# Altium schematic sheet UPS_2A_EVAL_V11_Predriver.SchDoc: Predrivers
size A4; CompanyName: Hedgehog OÜ; Revision: 1; SheetNumber: 2; SheetTotal: 6; DrawnBy: Peep Narusberg; Engineer: Peep Narusberg; Organization: Hedgehog OÜ; Address1: Waterloohain 5; Address2: 22769 Hamburg; Address3: Germany; Address4: tmc_info@trinamic.com
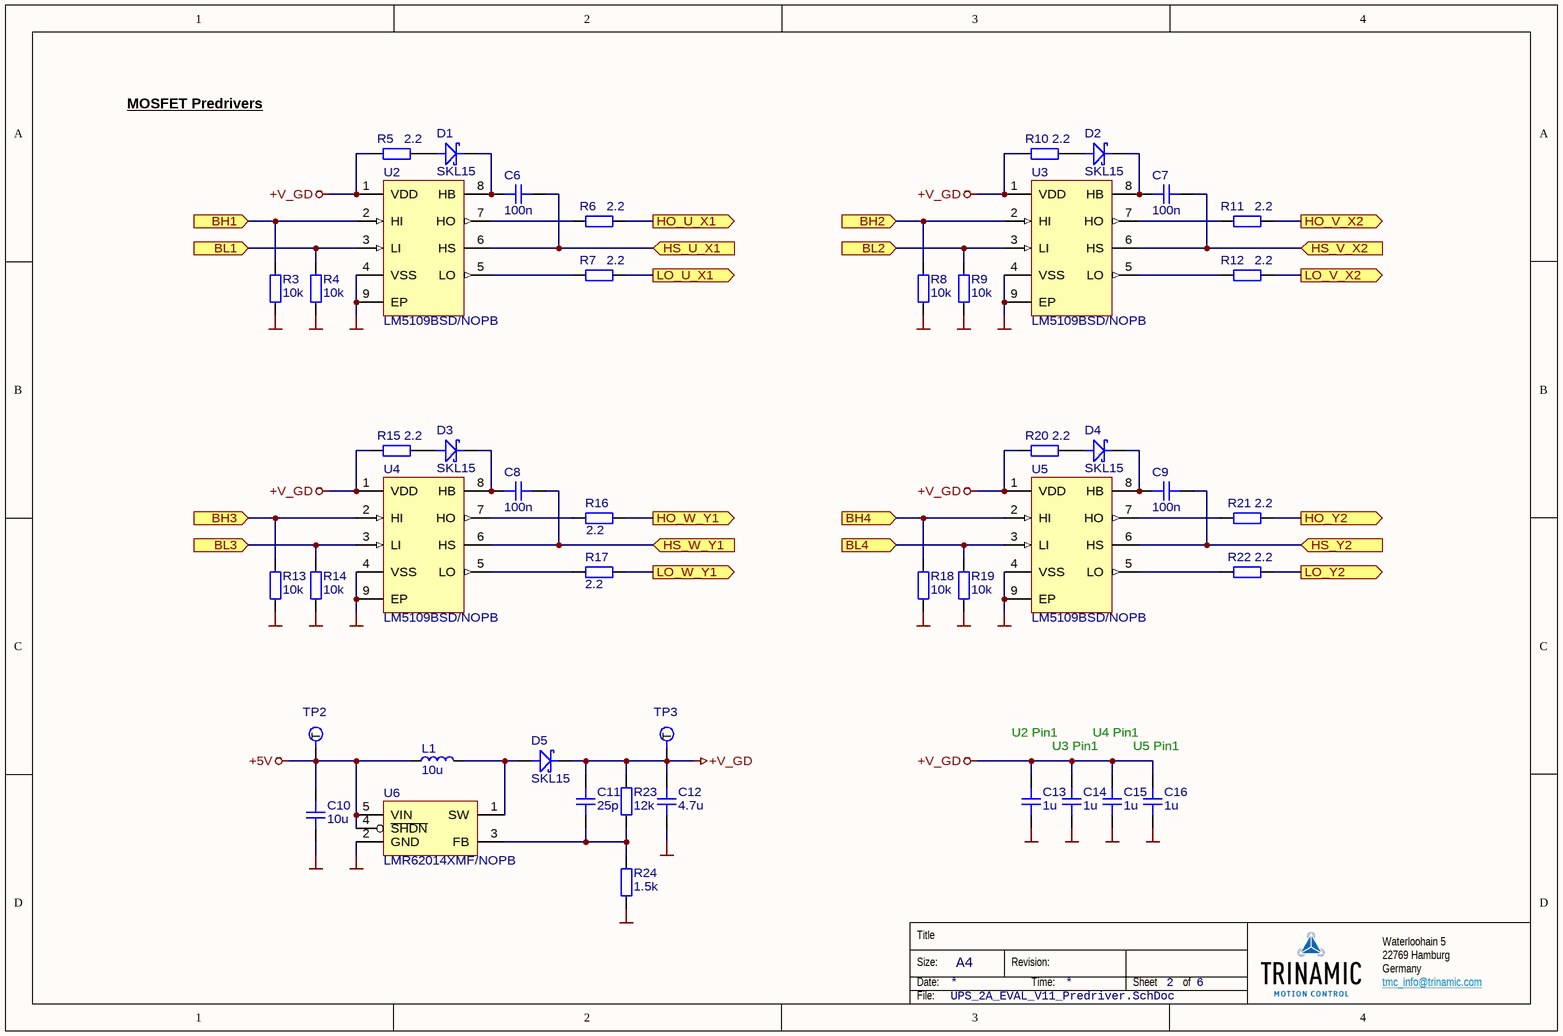
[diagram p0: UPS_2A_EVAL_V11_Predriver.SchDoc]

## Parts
C6  value 100n  [CAPC1608N]  (hidden comment: CAPC)
C7  value 100n  [CAPC1608N]  (hidden comment: CAPC)
C8  value 100n  [CAPC1608N]  (hidden comment: CAPC)
C9  value 100n  [CAPC1608N]  (hidden comment: CAPC)
C10  value 10u  [CAPC1608N]  (hidden comment: CAPC)
C11  value 25p  [CAPC1608N]  (hidden comment: CAPC)
C12  value 4.7u  [CAPC1608N]  (hidden comment: CAPC)
C13  value 1u  [CAPC1608N]  (hidden comment: CAPC)
C14  value 1u  [CAPC1608N]  (hidden comment: CAPC)
C15  value 1u  [CAPC1608N]  (hidden comment: CAPC)
C16  value 1u  [CAPC1608N]  (hidden comment: CAPC)
D1  Part Number: SKL15  [SODFL370X140-2N]  (hidden comment: DIO-SCHOTTKY)
D2  Part Number: SKL15  [SODFL370X140-2N]  (hidden comment: DIO-SCHOTTKY)
D3  Part Number: SKL15  [SODFL370X140-2N]  (hidden comment: DIO-SCHOTTKY)
D4  Part Number: SKL15  [SODFL370X140-2N]  (hidden comment: DIO-SCHOTTKY)
D5  Part Number: SKL15  [SODFL370X140-2N]  (hidden comment: DIO-SCHOTTKY)
L1  value 10u  [744031100]  (hidden comment: INDM)
R3  value 10k  [RESC1608N]  (hidden comment: RESC)
R4  value 10k  [RESC1608N]  (hidden comment: RESC)
R5  value 2.2  [RESC1608N]
R6  value 2.2  [RESC1608N]
R7  value 2.2  [RESC1608N]
R8  value 10k  [RESC1608N]  (hidden comment: RESC)
R9  value 10k  [RESC1608N]  (hidden comment: RESC)
R10  value 2.2  [RESC1608N]
R11  value 2.2  [RESC1608N]
R12  value 2.2  [RESC1608N]
R13  value 10k  [RESC1608N]  (hidden comment: RESC)
R14  value 10k  [RESC1608N]  (hidden comment: RESC)
R15  value 2.2  [RESC1608N]
R16  value 2.2  [RESC1608N]
R17  value 2.2  [RESC1608N]
R18  value 10k  [RESC1608N]  (hidden comment: RESC)
R19  value 10k  [RESC1608N]  (hidden comment: RESC)
R20  value 2.2  [RESC1608N]
R21  value 2.2  [RESC1608N]
R22  value 2.2  [RESC1608N]
R23  value 12k  [RESC1608N]  (hidden comment: RESC)
R24  value 1.5k  [RESC1608N]  (hidden comment: RESC)
TP2  +5V  [TP100P254]  (value not drawn)  (no BOM)
TP3  +V_GD  [TP100P254]  (value not drawn)  (no BOM)
U2  Part Number: LM5109BSD/NOPB  [PSON80P400X80_HS-9N]
U3  Part Number: LM5109BSD/NOPB  [PSON80P400X80_HS-9N]
U4  Part Number: LM5109BSD/NOPB  [PSON80P400X80_HS-9N]
U5  Part Number: LM5109BSD/NOPB  [PSON80P400X80_HS-9N]
U6  Part Number: LMR62014XMF/NOPB  [SOT95P280X145-5N]  (hidden comment: LMR62014)

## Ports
BH1 (in), BH2 (in), BH3 (in), BH4 (in), BL1 (in), BL2 (in), BL3 (in), BL4 (in), HO_U_X1 (out), HO_V_X2 (out), HO_W_Y1 (out), HO_Y2 (out), HS_U_X1 (in), HS_V_X2 (in), HS_W_Y1 (in), HS_Y2 (in), LO_U_X1 (out), LO_V_X2 (out), LO_W_Y1 (out), LO_Y2 (out)

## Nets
+5V: C10.2 L1.1 TP2.1(T) U6.4(~{SHDN}) U6.5(VIN)
+V_GD: C11.2 C12.2 C13.2 C14.2 C15.2 C16.2 D5.1 R5.1 R10.1 R15.1 R20.1 R23.2 TP3.1(T) U2.1(VDD) U3.1(VDD) U4.1(VDD) U5.1(VDD)
GND: C10.1 C12.1 C13.1 C14.1 C15.1 C16.1 R3.1 R4.1 R8.1 R9.1 R13.1 R14.1 R18.1 R19.1 R24.1 U2.4(VSS) U2.9(EP) U3.4(VSS) U3.9(EP) U4.4(VSS) U4.9(EP) U5.4(VSS) U5.9(EP) U6.2(GND)
BH1: R3.2 U2.2(HI) ; port BH1
BH2: R8.2 U3.2(HI) ; port BH2
BH3: R13.2 U4.2(HI) ; port BH3
BH4: R18.2 U5.2(HI) ; port BH4
BL1: R4.2 U2.3(LI) ; port BL1
BL2: R9.2 U3.3(LI) ; port BL2
BL3: R14.2 U4.3(LI) ; port BL3
BL4: R19.2 U5.3(LI) ; port BL4
HO_U_X1: R6.2 ; port HO_U_X1
HO_V_X2: R11.2 ; port HO_V_X2
HO_W_Y1: R16.2 ; port HO_W_Y1
HO_Y2: R21.2 ; port HO_Y2
HS_U_X1: C6.2 U2.6(HS) ; port HS_U_X1
HS_V_X2: C7.2 U3.6(HS) ; port HS_V_X2
HS_W_Y1: C8.2 U4.6(HS) ; port HS_W_Y1
HS_Y2: C9.2 U5.6(HS) ; port HS_Y2
LO_U_X1: R7.2 ; port LO_U_X1
LO_V_X2: R12.2 ; port LO_V_X2
LO_W_Y1: R17.2 ; port LO_W_Y1
LO_Y2: R22.2 ; port LO_Y2
NetC6_1: C6.1 D1.1 U2.8(HB)
NetC7_1: C7.1 D2.1 U3.8(HB)
NetC8_1: C8.1 D3.1 U4.8(HB)
NetC9_1: C9.1 D4.1 U5.8(HB)
NetC11_1: C11.1 R23.1 R24.2 U6.3(FB)
NetD1_2: D1.2 R5.2
NetD2_2: D2.2 R10.2
NetD3_2: D3.2 R15.2
NetD4_2: D4.2 R20.2
NetD5_2: D5.2 L1.2 U6.1(SW)
NetR6_1: R6.1 U2.7(HO)
NetR7_1: R7.1 U2.5(LO)
NetR11_1: R11.1 U3.7(HO)
NetR12_1: R12.1 U3.5(LO)
NetR16_1: R16.1 U4.7(HO)
NetR17_1: R17.1 U4.5(LO)
NetR21_1: R21.1 U5.7(HO)
NetR22_1: R22.1 U5.5(LO)

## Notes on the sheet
- MOSFET Predrivers
- U2 Pin1
- U3 Pin1
- U4 Pin1
- U5 Pin1

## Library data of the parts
C6-C9 = 20027: Ceramic chip capacitor; Manufacturer: Any; Part Number: 100n, 50V, X5R, 0603 (1608 metric) chip capacitor; Id: 20027; Voltage: 50V
C10 = 20111: Ceramic chip capacitor; Manufacturer: Any; Part Number: 10u, 10V, X5R, 0603 (1608 metric) chip capacitor; Id: 20111; Voltage: 10V
C11 = 20112: Ceramic chip capacitor; Manufacturer: Any; Part Number: 25p, 50V, C0G/NP0, 0603 (1608 metric) chip capacitor; Id: 20112; Voltage: 50V
C12 = 20113: Ceramic chip capacitor; Manufacturer: Any; Part Number: 4.7u, 25V, X5R, 0603 (1608 metric) chip capacitor; Id: 20113; Voltage: 25V
C13-C16 = 20077: Ceramic chip capacitor; Manufacturer: Any; Part Number: 1u, 25V, X5R, 0603 (1608 metric) chip capacitor; Id: 20077; Voltage: 25V
D1-D5 = 50567: Schottky Diode, pin1 cathode; Manufacturer: Diotec  Semiconductor; Id: 50567; Value: 1A, 50V
L1 = 60031: Molded inductor; Manufacturer: Wuerth; Id: 60031; Tolerance: 30; Current: 740m
R3 R4 R8 R9 R13 R14 R18 R19 = 10028: Chip Resistor; Manufacturer: Any; Part Number: 10k, 1%, 100mW, 0603 (1608 metric) chip resistor; Id: 10028; Power: 100mW; Tolerance: 1%
R5-R7 R10-R12 R15-R17 R20-R22 = 10041: Chip Resistor; Manufacturer: Any; Part Number: 2.2, 1%, 100mW, 0603 (1608 metric) chip resistor; Id: 10041; Power: 100mW; Tolerance: 1%
R23 = 10078: Chip Resistor; Manufacturer: Any; Part Number: 12k, 1%, 100mW, 0603 (1608 metric) chip resistor; Id: 10078; Power: 100mW; Tolerance: 1%
R24 = 10152: Chip Resistor; Manufacturer: Any; Part Number: 1.5k, 1%, 100mW, 0603 (1608 metric) chip resistor; Id: 10152; Power: 100mW; Tolerance: 1%
TP2 TP3 = 50094: Round testpoint; Id: 50094; Value: c160 (P100 probe)
U2-U5 = 50490: High Voltage 1A Peak Half Bridge Gate Driver; Manufacturer: Texas Instruments; Id: 50490; Value: 108V 1A
U6 = 50495: LMR62014 SIMPLE SWITCHER® 20Vout, 1.4A Step-Up Voltage Regulator in SOT-23; Manufacturer: Texas Instruments; Id: 50495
